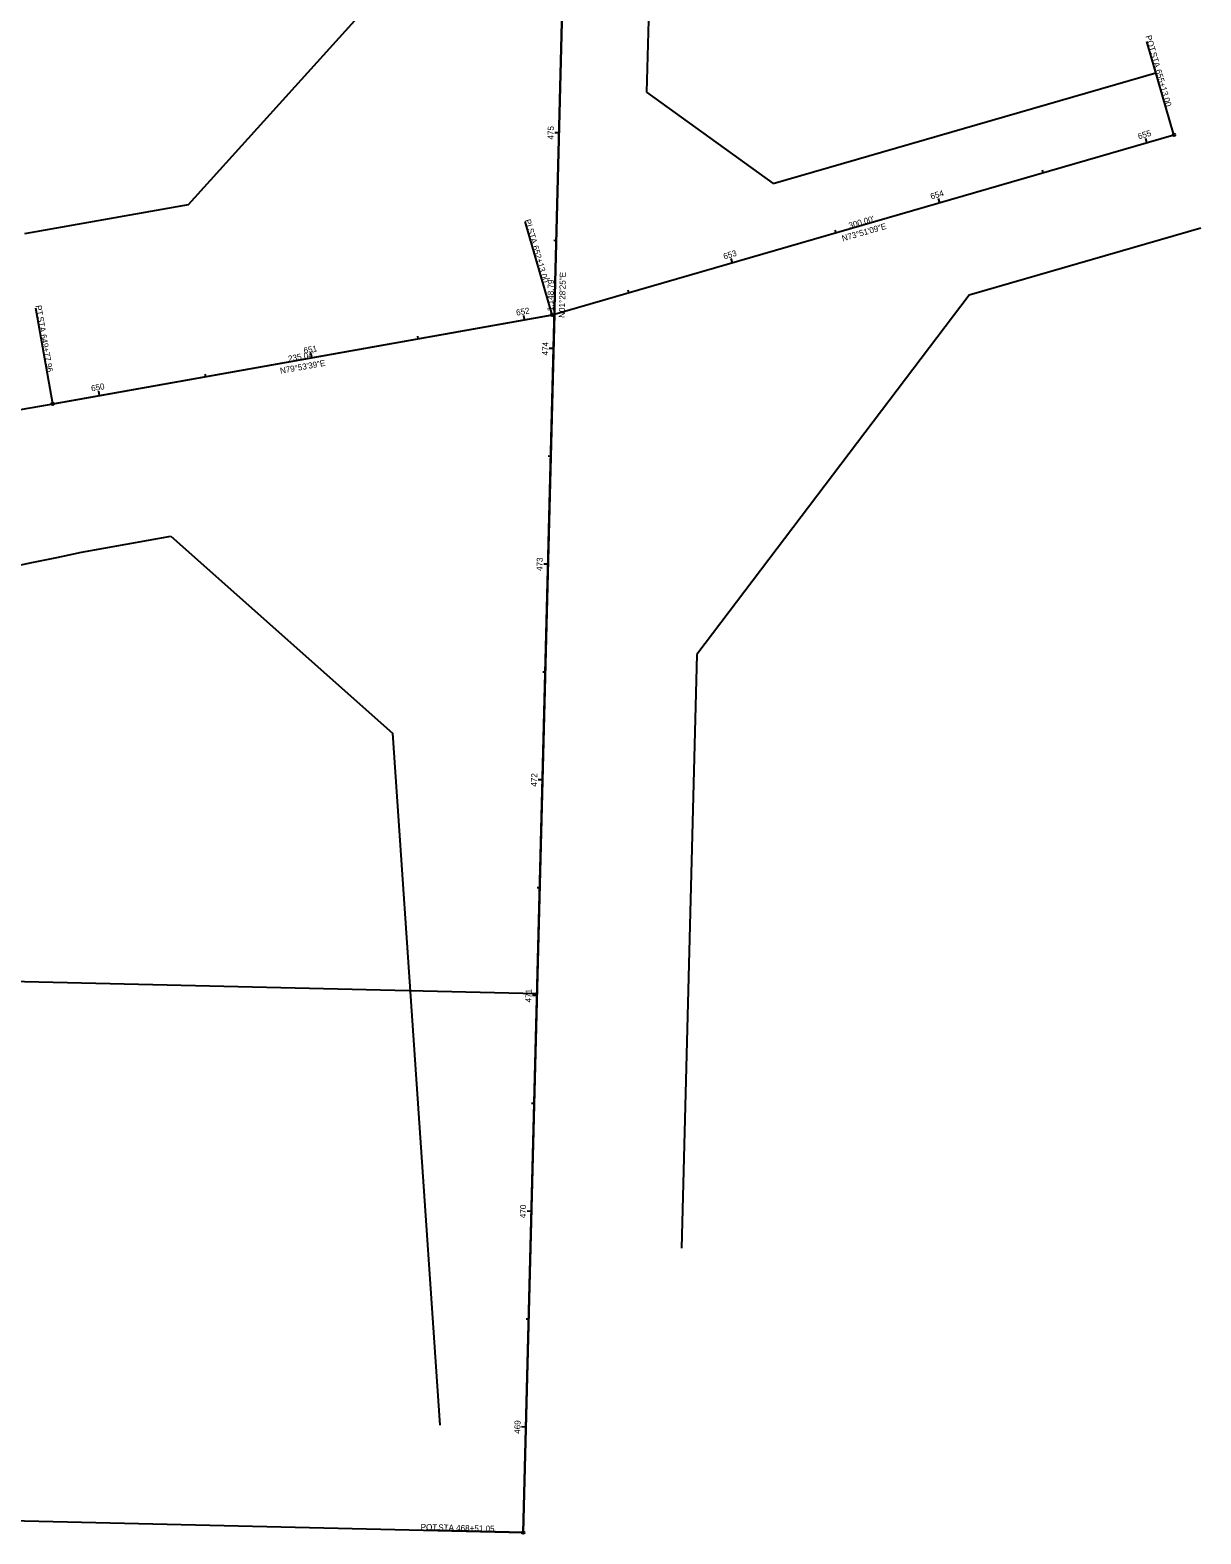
# Model space of a CAD drawing. Extents: x 1390087 to 1393932, y 303908 to 305061.
# Drawn here: x 1392092 to 1392634, y 303908 to 304605 of the extents above; entities that cross this region are included whole.
import ezdxf

# ---------------------------------------------------------------- set-up
doc = ezdxf.new("R2010")
doc.units = 0
for name, color, linetype in [('DV_X_Property_Line', 7, 'Continuous'), ('DV_X_Section_VMS_Line', 7, 'Continuous'), ('RW_X_CL', 7, 'Continuous'), ('RW_X_CL_100_Bearings', 7, 'Continuous'), ('RW_X_CL_100_Cardinal_Points', 7, 'Continuous'), ('RW_X_CL_100_Distances', 7, 'Continuous'), ('RW_X_CL_100_Stations', 7, 'Continuous'), ('RW_X_Esmt_SH', 7, 'Continuous'), ('SC_Scratch6', 7, 'Continuous')]:
    doc.layers.add(name, color=color, linetype=linetype)

msp = doc.modelspace()

# ---------------------------------------------------------------- linework, layer by layer
at = {"layer": 'DV_X_Property_Line'}
for p, q in [((1392103.26, 304431.59), (1392334.71, 304472.84)), ((1391713.86, 304172.54), (1392326.68, 304158.21)), ((1391708.02, 303922.61), (1392320.18, 303908.29))]:
    msp.add_line(p, q, dxfattribs=at)
at = {"layer": 'DV_X_Section_VMS_Line'}
msp.add_line((1392349.72, 305056.71), (1392320.18, 303908.29), dxfattribs=at)
at = {"layer": 'RW_X_CL'}
for p, q in [((1392349.72, 305056.71), (1392320.18, 303908.29)), ((1392320.18, 303908.29), (1392349.72, 305056.71)), ((1392333.59, 304472.64), (1392621.76, 304556.08)), ((1392333.59, 304472.64), (1392621.76, 304556.08)), ((1392102.2, 304431.4), (1392333.59, 304472.64)), ((1392102.2, 304431.4), (1392333.59, 304472.64))]:
    msp.add_line(p, q, dxfattribs=at)
msp.add_arc((1391097.92, 310072.28), 5729.58, 272.589038, 280.105736, dxfattribs=at)
msp.add_arc((1391097.92, 310072.28), 5729.58, 272.589038, 280.105736, dxfattribs=at)
at = {"layer": 'RW_X_CL_100_Cardinal_Points'}
for p, q in [((1392621.76, 304556.08), (1392609.24, 304599.3)), ((1392333.59, 304472.64), (1392321.08, 304515.87)), ((1392102.2, 304431.4), (1392094.3, 304475.7)), ((1392320.18, 303908.29), (1392275.2, 303909.45))]:
    msp.add_line(p, q, dxfattribs=at)
for centre in [(1392621.76, 304556.08), (1392333.59, 304472.64), (1392102.2, 304431.4), (1392320.18, 303908.29)]:
    msp.add_circle(centre, 0.6, dxfattribs=at)
at = {"layer": 'RW_X_CL_100_Stations'}
for p, q in [((1392336.87, 304557.03), (1392334.87, 304557.08)), ((1392609.27, 304552.46), (1392608.71, 304554.38)), ((1392561.24, 304538.56), (1392560.91, 304539.71)), ((1392513.21, 304524.65), (1392512.66, 304526.57)), ((1392465.19, 304510.74), (1392464.85, 304511.9)), ((1392335.59, 304507.04), (1392334.39, 304507.07)), ((1392417.16, 304496.84), (1392416.6, 304498.76)), ((1392369.13, 304482.93), (1392368.8, 304484.09)), ((1392320.79, 304470.36), (1392320.44, 304472.33)), ((1392271.57, 304461.59), (1392271.36, 304462.77)), ((1392222.34, 304452.82), (1392221.99, 304454.78)), ((1392334.3, 304457.06), (1392332.3, 304457.11)), ((1392173.12, 304444.04), (1392172.91, 304445.22)), ((1392123.89, 304435.27), (1392123.54, 304437.24)), ((1392333.01, 304407.08), (1392331.81, 304407.11)), ((1392331.73, 304357.09), (1392329.73, 304357.14)), ((1392330.44, 304307.11), (1392329.24, 304307.14)), ((1392329.16, 304257.13), (1392327.16, 304257.18)), ((1392327.87, 304207.14), (1392326.67, 304207.17)), ((1392326.59, 304157.16), (1392324.59, 304157.21)), ((1392325.3, 304107.18), (1392324.1, 304107.21)), ((1392324.01, 304057.19), (1392322.01, 304057.24)), ((1392322.73, 304007.21), (1392321.53, 304007.24)), ((1392321.44, 303957.23), (1392319.44, 303957.28))]:
    msp.add_line(p, q, dxfattribs=at)
at = {"layer": 'RW_X_Esmt_SH'}
for p, q in [((1392382.39, 304771.01), (1392377.37, 304575.85)), ((1392165.07, 304523.87), (1392268.84, 304638.64)), ((1392436.11, 304533.56), (1392613.41, 304584.89)), ((1392377.37, 304575.85), (1392436.11, 304533.56)), ((1392089.23, 304510.35), (1392165.07, 304523.87)), ((1392634.27, 304512.85), (1392526.85, 304481.75)), ((1392526.85, 304481.75), (1392400.68, 304315.31)), ((1392115.54, 304362.68), (1392156.93, 304370.05)), ((1392156.93, 304370.05), (1392259.71, 304278.76)), ((1392400.68, 304315.31), (1392393.6, 304040.08)), ((1392259.71, 304278.76), (1392281.57, 303958.12))]:
    msp.add_line(p, q, dxfattribs=at)
msp.add_arc((1390911.43, 310046.1), 5809.58, 278.249443, 281.961997, dxfattribs=at)
at = {"layer": 'SC_Scratch6'}
msp.add_line((1392334.71, 304472.97), (1392320.18, 303908.29), dxfattribs=at)

# ---------------------------------------------------------------- texts
at = {"layer": 'RW_X_CL_100_Bearings'}
for s, rotation, p in [('N73°51\'09"E', 16.14745, (1392468.33, 304506.66)), ('N01°28\'25"E', 88.52651, (1392339.47, 304471.26)), ('N79°53\'39"E', 10.10578, (1392207.79, 304445.35))]:
    msp.add_text(s, height=2.8, rotation=rotation, dxfattribs=at).set_placement(p)
at = {"layer": 'RW_X_CL_100_Cardinal_Points'}
for s, rotation, p in [('POT', 286.14745, (1392608.55, 304601.81)), (' STA. ', 286.14745, (1392610.53, 304594.96)), ('655+13.00', 286.14745, (1392613.13, 304586.01)), ('PI', 286.14745, (1392320.92, 304516.55)), (' STA. ', 286.14745, (1392321.84, 304513.36)), ('652+13.00', 286.14745, (1392324.43, 304504.4)), ('PT', 280.10578, (1392094.13, 304476.89)), (' STA. ', 280.10578, (1392094.89, 304472.61)), ('649+77.96', 280.10578, (1392096.53, 304463.43)), ('POT', 358.52651, (1392272.66, 303909.55)), (' STA. ', 358.52651, (1392279.79, 303909.37)), ('468+51.05', 358.52651, (1392289.11, 303909.13))]:
    msp.add_text(s, height=2.8, rotation=rotation, dxfattribs=at).set_placement(p)
at = {"layer": 'RW_X_CL_100_Distances'}
for s, rotation, p in [("300.00'", 16.14745, (1392471.48, 304512.6)), ("1,148.79'", 88.52651, (1392334.12, 304474.42)), ("235.04'", 10.10578, (1392211.55, 304450.93))]:
    msp.add_text(s, height=2.8, rotation=rotation, dxfattribs=at).set_placement(p)
at = {"layer": 'RW_X_CL_100_Stations'}
for s, rotation, p in [('475', 88.52651, (1392334.29, 304553.89)), ('655', 16.14745, (1392605.49, 304553.97)), ('654', 16.14745, (1392509.37, 304526.14)), ('653', 16.14745, (1392413.39, 304498.35)), ('652', 10.10578, (1392317.19, 304472.26)), ('651', 10.10578, (1392218.73, 304454.71)), ('474', 88.52651, (1392331.72, 304453.85)), ('650', 10.10578, (1392120.24, 304437.16)), ('473', 88.52651, (1392329.15, 304353.96)), ('472', 88.52651, (1392326.58, 304253.98)), ('471', 88.52651, (1392324, 304154)), ('470', 88.52651, (1392321.43, 304053.99)), ('469', 88.52651, (1392318.86, 303954.07))]:
    msp.add_text(s, height=2.8, rotation=rotation, dxfattribs=at).set_placement(p)

doc.saveas('drawing.dxf')
